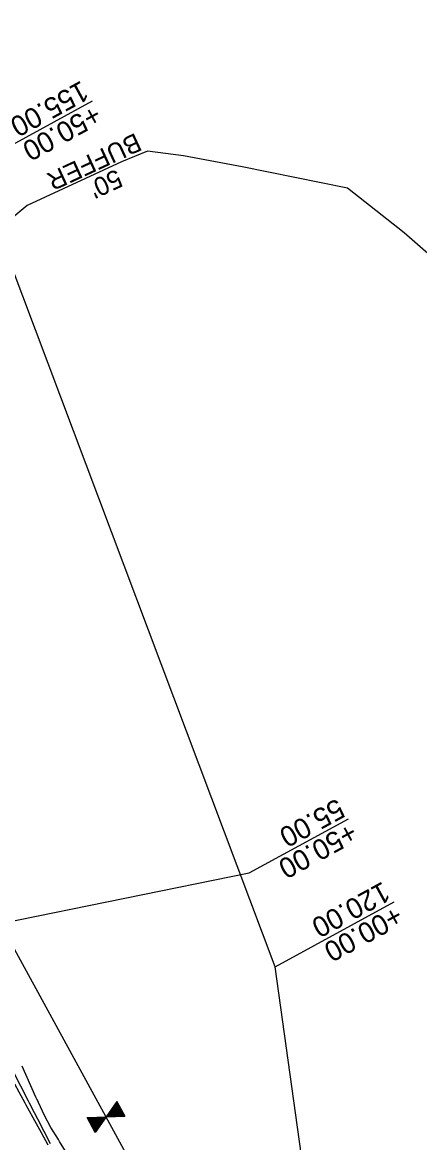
# Model space of a CAD drawing. Extents: x 1627557 to 1636561, y 783843 to 794002.
# Drawn here: x 1628204.6 to 1628321.8, y 784710.3 to 785040.7 of the extents above; entities that cross this region are included whole.
import ezdxf

# ---------------------------------------------------------------- set-up
doc = ezdxf.new("R2010")
doc.units = 0
for name, color, linetype in [('25 FT Buffer', 7, 'Continuous'), ('GATE', 7, 'Continuous'), ('R_Clearzone', 7, 'Continuous'), ('R_Ditch', 7, 'Continuous'), ('R_Proposed Const Limits', 7, 'Continuous'), ('R_ROW', 7, 'Continuous'), ('R_ROW Annot', 7, 'Continuous'), ('R_Temp Const Easement', 7, 'Continuous'), ('R_Temp Easement Annot', 7, 'Continuous')]:
    doc.layers.add(name, color=color, linetype=linetype)

msp = doc.modelspace()

# ---------------------------------------------------------------- linework, layer by layer
at = {"layer": '25 FT Buffer'}
msp.add_lwpolyline([(1628560.94, 785155.55), (1628549.76, 785147.87), (1628517.02, 785118.79), (1628477.49, 784998.68), (1628405.7, 784961.56), (1628353.93, 784946.56), (1628317.3, 784978.64), (1628300.57, 784991.85), (1628269.43, 784998.1), (1628252.11, 785001.38), (1628241.51, 785002.7), (1628233.9, 784999.54), (1628206.02, 784986.66), (1628193.93, 784976.66), (1628193.21, 784975.34), (1628183.18, 784944.53), (1628141.61, 784911.68), (1628128.73, 784912.02)], dxfattribs=at)
at = {"layer": 'GATE'}
for p, q in [((1628231.64, 784721.23), (1628233.41, 784718)), ((1628231.71, 784721.33), (1628233.52, 784718)), ((1628231.77, 784721.42), (1628233.63, 784718.01)), ((1628231.84, 784721.51), (1628233.74, 784718.01)), ((1628231.9, 784721.6), (1628233.86, 784718.01)), ((1628231.96, 784721.69), (1628233.97, 784718.02)), ((1628232.03, 784721.78), (1628234.08, 784718.02)), ((1628232.09, 784721.88), (1628234.19, 784718.03)), ((1628232.15, 784721.97), (1628234.3, 784718.03)), ((1628232.22, 784722.06), (1628234.41, 784718.03)), ((1628232.28, 784722.15), (1628234.53, 784718.04)), ((1628232.35, 784722.24), (1628234.64, 784718.04)), ((1628232.41, 784722.33), (1628234.75, 784718.05)), ((1628232.47, 784722.43), (1628234.86, 784718.05)), ((1628229.34, 784717.93), (1628229.39, 784717.85)), ((1628229.41, 784718.02), (1628229.5, 784717.86)), ((1628229.47, 784718.11), (1628229.61, 784717.86)), ((1628229.54, 784718.21), (1628229.72, 784717.87)), ((1628229.6, 784718.3), (1628229.83, 784717.87)), ((1628229.66, 784718.39), (1628229.94, 784717.87)), ((1628229.73, 784718.48), (1628230.06, 784717.88)), ((1628229.79, 784718.57), (1628230.17, 784717.88)), ((1628229.86, 784718.66), (1628230.28, 784717.89)), ((1628229.92, 784718.76), (1628230.39, 784717.89)), ((1628229.98, 784718.85), (1628230.5, 784717.89)), ((1628230.05, 784718.94), (1628230.62, 784717.9)), ((1628230.11, 784719.03), (1628230.73, 784717.9)), ((1628230.18, 784719.12), (1628230.84, 784717.91)), ((1628230.24, 784719.21), (1628230.95, 784717.91)), ((1628230.3, 784719.31), (1628231.06, 784717.91)), ((1628230.37, 784719.4), (1628231.17, 784717.92)), ((1628230.43, 784719.49), (1628231.29, 784717.92)), ((1628230.49, 784719.58), (1628231.4, 784717.93)), ((1628230.56, 784719.67), (1628231.51, 784717.93)), ((1628230.62, 784719.77), (1628231.62, 784717.93)), ((1628230.69, 784719.86), (1628231.73, 784717.94)), ((1628230.75, 784719.95), (1628231.84, 784717.94)), ((1628230.81, 784720.04), (1628231.96, 784717.95)), ((1628230.88, 784720.13), (1628232.07, 784717.95)), ((1628230.94, 784720.22), (1628232.18, 784717.95)), ((1628231.01, 784720.32), (1628232.29, 784717.96)), ((1628231.07, 784720.41), (1628232.4, 784717.96)), ((1628231.13, 784720.5), (1628232.51, 784717.97)), ((1628231.2, 784720.59), (1628232.63, 784717.97)), ((1628231.26, 784720.68), (1628232.74, 784717.97)), ((1628231.32, 784720.77), (1628232.85, 784717.98)), ((1628231.39, 784720.87), (1628232.96, 784717.98)), ((1628231.45, 784720.96), (1628233.07, 784717.99)), ((1628231.52, 784721.05), (1628233.18, 784717.99)), ((1628231.58, 784721.14), (1628233.3, 784717.99)), ((1628223.78, 784717.66), (1628226.14, 784713.33)), ((1628223.9, 784717.66), (1628226.21, 784713.42)), ((1628224.01, 784717.66), (1628226.27, 784713.51)), ((1628224.12, 784717.67), (1628226.33, 784713.6)), ((1628224.23, 784717.67), (1628226.4, 784713.7)), ((1628224.34, 784717.67), (1628226.46, 784713.79)), ((1628224.45, 784717.68), (1628226.53, 784713.88)), ((1628224.57, 784717.68), (1628226.59, 784713.97)), ((1628224.68, 784717.69), (1628226.65, 784714.06)), ((1628224.79, 784717.69), (1628226.72, 784714.15)), ((1628224.9, 784717.69), (1628226.78, 784714.25)), ((1628225.01, 784717.7), (1628226.85, 784714.34)), ((1628225.12, 784717.7), (1628226.91, 784714.43)), ((1628225.24, 784717.71), (1628226.97, 784714.52)), ((1628225.35, 784717.71), (1628227.04, 784714.61)), ((1628225.46, 784717.71), (1628227.1, 784714.7)), ((1628225.57, 784717.72), (1628227.16, 784714.8)), ((1628225.68, 784717.72), (1628227.23, 784714.89)), ((1628225.79, 784717.73), (1628227.29, 784714.98)), ((1628225.91, 784717.73), (1628227.36, 784715.07)), ((1628226.02, 784717.73), (1628227.42, 784715.16)), ((1628226.13, 784717.74), (1628227.48, 784715.26)), ((1628226.24, 784717.74), (1628227.55, 784715.35)), ((1628226.35, 784717.75), (1628227.61, 784715.44)), ((1628226.46, 784717.75), (1628227.68, 784715.53)), ((1628226.58, 784717.75), (1628227.74, 784715.62)), ((1628226.69, 784717.76), (1628227.8, 784715.71)), ((1628226.8, 784717.76), (1628227.87, 784715.81)), ((1628226.91, 784717.77), (1628227.93, 784715.9)), ((1628227.02, 784717.77), (1628227.99, 784715.99)), ((1628227.14, 784717.77), (1628228.06, 784716.08)), ((1628227.25, 784717.78), (1628228.12, 784716.17)), ((1628227.36, 784717.78), (1628228.19, 784716.26)), ((1628227.47, 784717.79), (1628228.25, 784716.36)), ((1628227.58, 784717.79), (1628228.31, 784716.45)), ((1628227.69, 784717.79), (1628228.38, 784716.54)), ((1628227.81, 784717.8), (1628228.44, 784716.63)), ((1628227.92, 784717.8), (1628228.51, 784716.72)), ((1628228.03, 784717.81), (1628228.57, 784716.82)), ((1628228.14, 784717.81), (1628228.63, 784716.91)), ((1628228.25, 784717.81), (1628228.7, 784717)), ((1628228.36, 784717.82), (1628228.76, 784717.09)), ((1628228.48, 784717.82), (1628228.82, 784717.18)), ((1628228.59, 784717.83), (1628228.89, 784717.27)), ((1628228.7, 784717.83), (1628228.95, 784717.37)), ((1628228.81, 784717.83), (1628229.02, 784717.46)), ((1628228.92, 784717.84), (1628229.08, 784717.55)), ((1628229.03, 784717.84), (1628229.14, 784717.64)), ((1628229.15, 784717.85), (1628229.21, 784717.73)), ((1628229.26, 784717.85), (1628229.27, 784717.82))]:
    msp.add_line(p, q, dxfattribs=at)
for points in [[(1628232.48, 784722.44), (1628229.29, 784717.85), (1628234.88, 784718.05)], [(1628223.7, 784717.65), (1628229.29, 784717.85), (1628226.1, 784713.26)]]:
    msp.add_lwpolyline(points, close=True, dxfattribs=at)
at = {"layer": 'R_Clearzone'}
msp.add_lwpolyline([(1628212.19, 784709.52), (1628210.21, 784713.15), (1628208.3, 784716.66), (1628206.26, 784720.4), (1628206.12, 784720.66), (1628205.76, 784721.32), (1628205.43, 784721.93), (1628200.64, 784730.7)], dxfattribs=at)
at = {"layer": 'R_Ditch'}
msp.add_lwpolyline([(1628212.93, 784709.93), (1628211.03, 784713.59), (1628209.19, 784717.15), (1628207.24, 784720.93), (1628207.11, 784721.2), (1628206.76, 784721.86), (1628206.45, 784722.48), (1628201.89, 784731.38)], dxfattribs=at)
at = {"layer": 'R_Proposed Const Limits'}
msp.add_lwpolyline([(1628218.35, 784706.19), (1628215.6, 784710.6), (1628215.5, 784710.77), (1628215.23, 784711.18), (1628213.05, 784714.69), (1628211.19, 784718.23), (1628209.37, 784722.09), (1628209.24, 784722.36), (1628208.92, 784723.04), (1628208.63, 784723.67), (1628204.53, 784732.82)], dxfattribs=at)
at = {"layer": 'R_ROW'}
msp.add_line((1628269.98, 784643.22), (1628198.17, 784774.92), dxfattribs=at)
at = {"layer": 'R_ROW Annot'}
msp.add_lwpolyline([(1628198.17, 784774.92), (1628271.5, 784789.81), (1628300.85, 784805.82)], dxfattribs=at)
at = {"layer": 'R_Temp Const Easement'}
for p, q in [((1628279.18, 784762.14), (1628190.23, 784998.39)), ((1628308.94, 784550.4), (1628279.18, 784762.14))]:
    msp.add_line(p, q, dxfattribs=at)
at = {"layer": 'R_Temp Easement Annot'}
for points in [[(1628190.23, 784998.39), (1628225.35, 785017.53)], [(1628279.18, 784762.14), (1628314.3, 784781.28)]]:
    msp.add_lwpolyline(points, dxfattribs=at)

# ---------------------------------------------------------------- texts
at = {"layer": '25 FT Buffer'}
for s, p in [('BUFFER', (1628238.02, 785008.23)), ("50'", (1628232.43, 784997.57))]:
    msp.add_text(s, height=5.5, rotation=204.7973, dxfattribs=at).set_placement(p)
at = {"layer": 'R_ROW Annot'}
for s, p in [('55.00', (1628297.5, 784811.96)), ('+50.00', (1628301.33, 784804.94))]:
    msp.add_text(s, height=6, rotation=208.601, dxfattribs=at).set_placement(p)
at = {"layer": 'R_Temp Easement Annot'}
for s, p in [('155.00', (1628222, 785023.68)), ('+50.00', (1628225.83, 785016.66)), ('120.00', (1628310.95, 784787.43)), ('+00.00', (1628314.78, 784780.41))]:
    msp.add_text(s, height=6, rotation=208.601, dxfattribs=at).set_placement(p)

doc.saveas('drawing.dxf')
